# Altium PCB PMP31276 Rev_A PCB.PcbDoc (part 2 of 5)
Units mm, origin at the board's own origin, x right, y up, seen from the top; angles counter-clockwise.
Board outline 228.6 x 203.2 mm, 4 copper layers (Top Layer, Layer 1, Layer 2, Bottom Layer), stack 1.998 mm thick; 375 components, 187 nets, 994 pads, 546 vias.
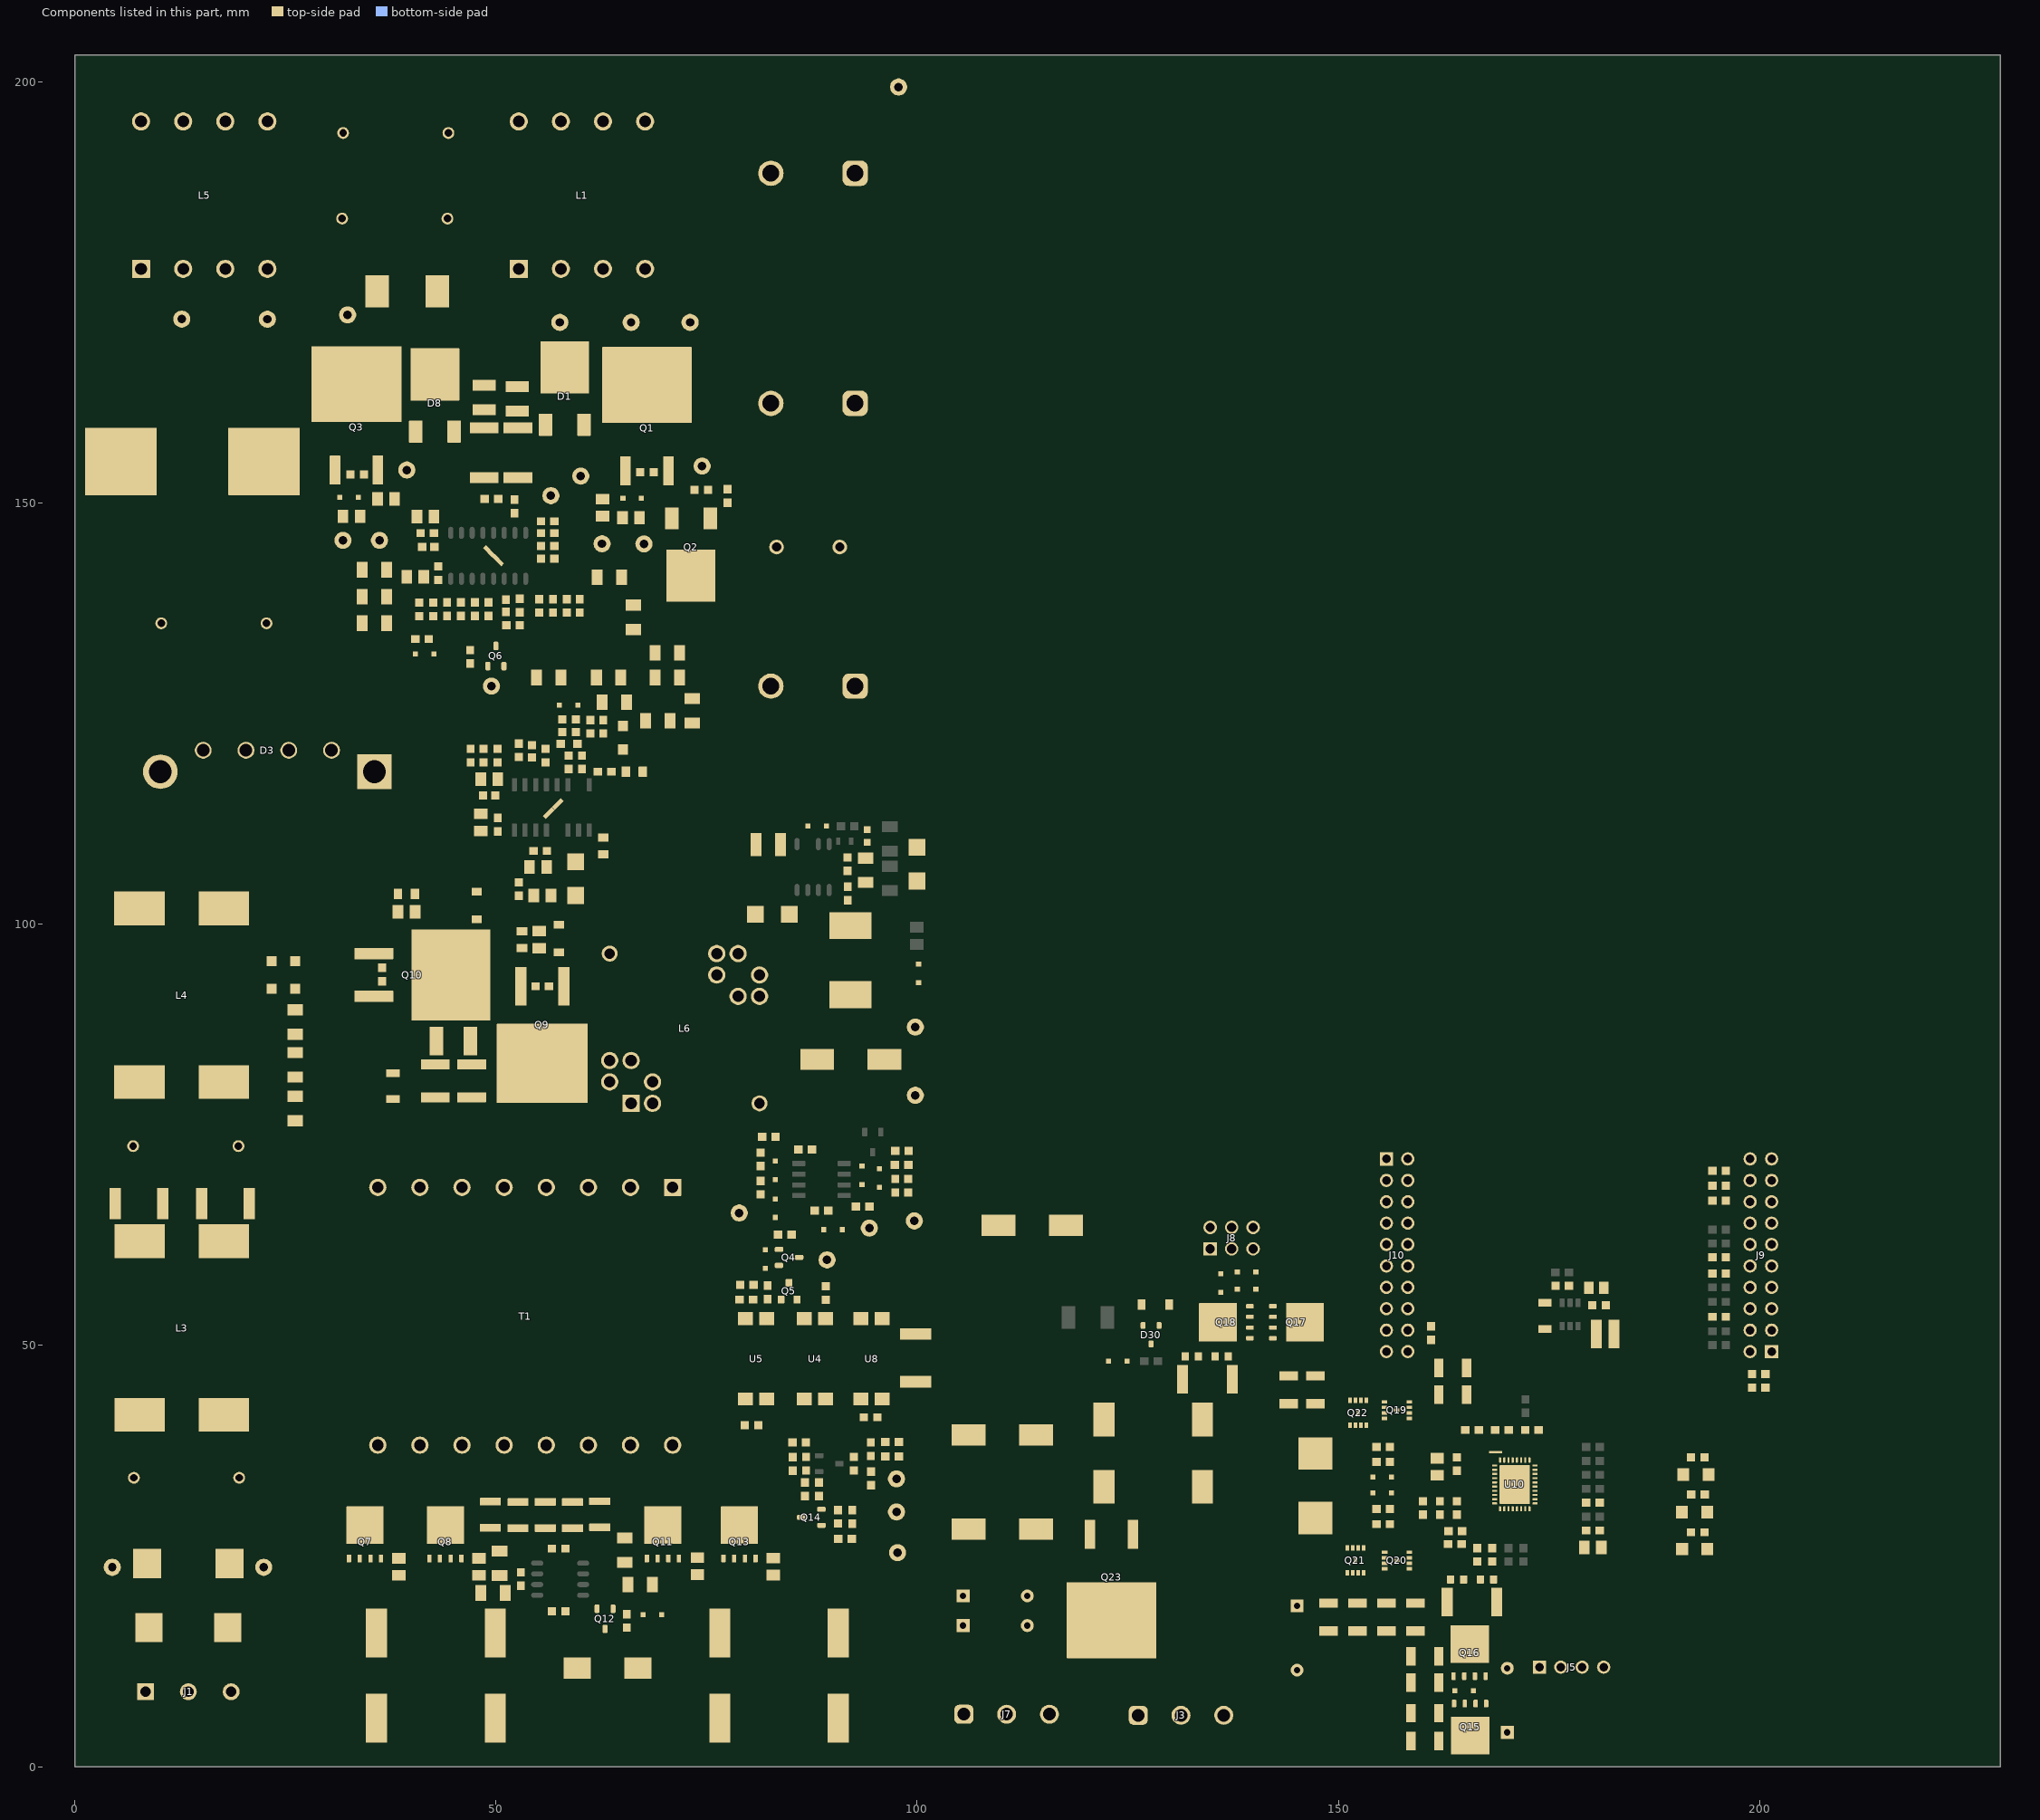
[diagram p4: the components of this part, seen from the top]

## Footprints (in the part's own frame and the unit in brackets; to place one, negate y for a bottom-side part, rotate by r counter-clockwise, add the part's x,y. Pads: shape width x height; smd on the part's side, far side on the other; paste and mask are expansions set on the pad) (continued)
FP-750314724_PTH_XFRMR_23MM5_26MM0-MFG [mm]
  rrect5% 2.15x2.15 hole 1.4 paste-2539.97 mask+0: 1(-8.75,7.5)
  round 2.15 hole 1.4 paste-2539.97 mask+0: 2(-8.75,2.5) 3(-8.75,-2.5) 4(-8.75,-7.5) 5(8.75,-7.5) 6(8.75,-2.5) 7(8.75,2.5) 8(8.75,7.5)
  silkscreen extent -12.47,-13 11.75,13, body extent -11.85,-13.1 11.85,13.1, height 0.25
FP-750371772r00_PTH16_41MM9_44MM0-MFG [mm]
  rrect5% 2.05x2.05 hole 1.35 paste-2539.97 mask+0: 1(-15.3,17.5)
  round 2.05 hole 1.35 paste-2539.97 mask+0: 2(-15.3,12.5) 3(-15.3,7.5) 4(-15.3,2.5) 5(-15.3,-2.5) 6(-15.3,-7.5) 7(-15.3,-12.5) 8(-15.3,-17.5) 9(15.3,-17.5) 10(15.3,-12.5) 11(15.3,-7.5) 12(15.3,-2.5) 13(15.3,2.5) 14(15.3,7.5) 15(15.3,12.5) 16(15.3,17.5)
  silkscreen extent -21.67,-22 20.95,22, body extent -21.05,-22.1 21.05,22.1, height 0.25
FP-750371775r00_PTH_22MM0_22MM0-MFG [mm]
  rrect5% 2.05x2.05 hole 1.35 paste-2539.97 mask+0: 1(-8.89,6.35)
  round 2.05 hole 1.35 paste-2539.97 mask+0: 2(-8.89,3.81) 3(-6.35,3.81) 4(3.81,-6.35) 5(3.81,-8.89) 6(6.35,-8.89) 7(8.89,-6.35) 8(8.89,-3.81) 9(6.35,-3.81) 10(-3.81,6.35) 11(-3.81,8.89) 12(-6.35,8.89)
  round 1.9 hole 1.25 paste-2539.97 mask+0: 13(8.89,8.89) 14(-8.89,-8.89)
  silkscreen extent -11.72,-11 11,11, body extent -11.1,-11.1 11.1,11.1, height 0.25
FP-7443081030_SMT_IND_9MM4_6MM2-MFG [mm]
  rrect4% 3.2x2.54 smd paste+0 mask+0: 1(-3.6,0) 2(3.6,0)
  silkscreen extent -5.9,-3.25 4.85,3.25, body extent -5.3,-3.35 5.3,3.35, height 0.25
FP-560050316012_0603-IPC_B [mm]
  rrect12% 0.86x0.962 smd paste+0 mask+0: 1(-0.776,0) 2(0.776,0)
  silkscreen extent -1.21,-0.88 1.21,0.88, body extent -1.46,-0.73 1.46,0.73, height 0.25
FP-885012206125_0603-IPC_B [mm]
  rrect10% 1.032x0.96 smd paste+0 mask+0: 1(-0.714,0) 2(0.714,0)
  silkscreen extent -1.23,-0.88 1.23,0.88, body extent -1.48,-0.73 1.48,0.73, height 0.25
FP-885012208094_1206-MFG [mm]
  rrect11% 0.9x1.6 smd paste+0 mask+0: 1(-1.55,0) 2(1.55,0)
  silkscreen extent -0.72,-0.95 0.72,0.95, body extent -2.1,-1.05 2.1,1.05, height 0.25
FP-885012209073_1210-MFG [mm]
  rrect11% 0.9x2.5 smd paste+0 mask+0: 1(-1.55,0) 2(1.55,0)
  silkscreen extent -0.72,-1.4 0.72,1.4, body extent -2.1,-1.5 2.1,1.5, height 0.25
FP-B57371V2474J060_0603-MFG [mm]
  rrect10% 1x1 smd paste+0 mask+0: 1(-1,0) 2(1,0)
  silkscreen extent -0.13,-0.48 0.13,0.48, body extent -1.6,-0.6 1.6,0.6, height 0.25
FP-BSS84LT1G_SOT-23-3-318-08-MFG [mm]
  rrect13% 0.9x0.8 smd paste+0 mask+0: 1(-1,0.95) 2(-1,-0.95) 3(1,0)
  silkscreen extent -0.7,-1.52 0.7,1.52, body extent -1.55,-1.62 1.55,1.62, height 0.25
FP-C0603C221J5GAC7867_0603-IPC_B [mm]
  rrect10% 1.007x0.958 smd paste+0 mask+0: 1(-0.726,0) 2(0.726,0)
  silkscreen extent -1.23,-0.88 1.23,0.88, body extent -1.48,-0.73 1.48,0.73, height 0.25
FP-CKC18C103KWGACAUTO_1812-MFG [mm]
  rrect8% 1.2x3.4 smd paste+0 mask+0: 1(-1.95,0) 2(1.95,0)
  silkscreen extent -0.97,-1.75 0.97,1.75, body extent -2.65,-1.85 2.65,1.85, height 0.25
FP-IPB60R105CFD7ATMA1_D2PAK-MFG [mm]
  rrect7% 1.35x4.6 smd paste-1000 mask+0: 1(-2.54,-5.775) 3(2.54,-5.775)
  rrect1% 10.8x9.4 smd paste-1000 mask+0: 4(0,3.375)
  silkscreen extent -5.1,-2.73 5.1,-1.7, body extent -5.5,-8.18 5.5,8.18, height 0.25
FP-ISC0603NLSATMA1_TDSON-8-MFG [mm]
  rrect20% 0.5x0.925 smd paste-1000 mask+0: 1(-1.905,-2.865) 2(-0.635,-2.865) 3(0.635,-2.865) 4(1.905,-2.865)
  rrect2% 4.41x4.455 smd paste-1000 mask+0: 5-6-7-8(0,1.098)
  silkscreen extent -2.68,-4.03 2.68,3.05, body extent -2.78,-3.43 2.78,3.42, height 0.25
FP-SF-3812F1500T-2_3812-MFG [mm]
  rrect3% 3.25x3.43 smd paste+0 mask+0: 1(-4.675,0) 2(4.675,0)
  silkscreen extent -2.68,-1.65 2.68,1.65, body extent -6.4,-1.82 6.4,1.82, height 0.25
FP-V9733E1-LP_THERMAL_HEATSINK_25MM0_42MM0-MFG [mm]
  rrect2% 4.1x4.1 hole 2.7 paste-2539.97 mask+0: 1(-12.7,-0.5)
  round 4.1 hole 2.7 paste-2539.97 mask+0: 2(12.7,-0.5)
  silkscreen extent -21.12,-12.62 21.12,12.62, body extent -21.22,-12.73 21.22,12.73, height 0.25
GBU [mm] "Comchip / Diodes Inc diode bridge"
  round 2 hole 1.5: 1(-7.62,0) 2(-2.54,0) 3(2.54,0) 4(7.62,0)
  silkscreen extent -11.15,-2.28 11.15,1.28, body extent -11.15,-2.28 11.15,1.28, height 21.55
IEC_HighVoltage_Small [mm]
  silkscreen extent -2.72,-2.24 2.72,2.47
IEC_HotSurface_Small [mm]
  silkscreen extent -2.72,-2.36 2.72,2.35
Keystone5000 [mil] "For Keystone 500x miniature loop terminals"
  round 80 hole 40: 1(0,0)
  silkscreen extent -52,-52 52,52, body extent -49,-49 49,49, height 182
Keystone5001 [mil] "For Keystone 500x miniature loop terminals"
  round 80 hole 40: 1(0,0)
  silkscreen extent -52,-52 52,52, body extent -49,-49 49,49, height 182
Keystone5002 [mil] "For Keystone 500x miniature loop terminals"
  round 80 hole 40: 1(0,0)
  silkscreen extent -52,-52 52,52, body extent -49,-49 49,49, height 182
Keystone5004 [mil] "For Keystone 500x miniature loop terminals"
  round 80 hole 40: 1(0,0)
  silkscreen extent -52,-52 52,52, body extent -49,-49 49,49, height 182
Mill-Max_999-11-113-10-000000 [mil] "Shorting Jumper, 7.62mm, 2 Position, Gold, TH"
  rect 60x60 hole 30: 1(-150,0)
  round 60 hole 30: 2(150,0)
  silkscreen extent -102,-12 98,12, body extent -161,-11 161,11, height 105
Net-Tie_10milWide_30milLong [mil] "10mil net tie, no solder mask opening, no solder paste"
  rect 30x10 smd paste-5 mask-5: 1(-15,0) 2(15,0)
Net-Tie_20milWide_60milLong [mil] "20mil net tie, no solder mask opening, no solder paste"
  rect 60x20 smd paste-10 mask-10: 1(-30,0) 2(30,0)
On-Shore_ED120_3DS [mm] "ONSHORE"
  rrect5% 2x2 hole 1.25: 1(-5.08,0)
  round 2 hole 1.25: 2(0,0) 3(5.08,0)
  silkscreen extent -8.14,-4 7.5,5, body extent -8.32,-4 7.62,5, height 13
Power_WDFN-8 [mm] "SMD, 8-Leads, Body 3.3x3.3mm, Pitch 0.65mm"
  rect 0.66x0.42 smd: 1(-1.47,0.975) 2(-1.47,0.325) 3(-1.47,-0.325) 4(-1.47,-0.975) 5(1.47,-0.975) 6(1.47,-0.325) 7(1.47,0.325) 8(1.47,0.975) 9(0,0)
  Top Layer region: 0.25,1.73 -0.32,1.73 -0.32,1.185 -0.5,1.185 -0.5,-1.185 -0.32,-1.185 -0.32,-1.73 0.25,-1.73 0.25,-1.185 1.33,-1.185 1.33,1.185 0.25,1.185
  silkscreen extent -1.9,-1.65 1.65,1.75, body extent -1.65,-1.65 1.65,1.65, height 0.81
RRV0036A-MFG [mm]
  rrect40% 0.6x0.25 smd paste+0 mask+0: 1(-2.4,2.25) 2(-2.4,1.75) 3(-2.4,1.25) 4(-2.4,0.75) 5(-2.4,0.25) 6(-2.4,-0.25) 7(-2.4,-0.75) 8(-2.4,-1.25) 9(-2.4,-1.75) 10(-2.4,-2.25) 19(2.4,-2.25) 20(2.4,-1.75) 21(2.4,-1.25) 22(2.4,-0.75) 23(2.4,-0.25) 24(2.4,0.25) 25(2.4,0.75) 26(2.4,1.25) 27(2.4,1.75) 28(2.4,2.25)
  rrect40% 0.25x0.6 smd paste+0 mask+0: 11(-1.75,-2.9) 12(-1.25,-2.9) 13(-0.75,-2.9) 14(-0.25,-2.9) 15(0.25,-2.9) 16(0.75,-2.9) 17(1.25,-2.9) 18(1.75,-2.9) 29(1.75,2.9) 30(1.25,2.9) 31(0.75,2.9) 32(0.25,2.9) 33(-0.25,2.9) 34(-0.75,2.9) 35(-1.25,2.9) 36(-1.75,2.9)
  rrect3% 3.6x4.6 smd paste-1000 mask+0: 37(0,0)
  silkscreen extent -3.4,-3.05 2.55,3.05, body extent -2.8,-3.3 2.8,3.3, height 0.25
S237 [mm] "EPCOS"
  round 1.75 hole 1.1: 1(-3.75,0) 2(3.75,0)
  silkscreen extent -7.5,-3.5 7.5,3.5, body extent -7.47,-3.5 7.47,3.5, height 21.99
SM_RADIAL_10BMM [mm] "Nichicon 10x10"
  rect 4x2.5 smd: 1(-4,0) 2(4,0)
  silkscreen extent -5.25,-5.25 5.25,5.25, body extent -5.25,-5.25 5.25,5.25, height 10.5
SMA [mm] "Molded Diode, 2-Leads, Body 4.3x2.6mm, IPC Medium Density, based on OnSemi component dimensions and land pattern"
  rect 2x2 smd: 1(-2,0) 2(2,0)
  silkscreen extent -3.66,-1.57 2.79,1.57, body extent -2.6,-1.3 2.6,1.3, height 2.42
SMC [mil] "Molded Diode, 2-Leads, Body 6.9x5.8mm, IPC Medium Density, based on OnSemi component dimensions and land patterns"
  rect 110x150 smd: 1(-140.49,0) 2(140.49,0)
  silkscreen extent -221,-123 189,124, body extent -156,-116 156,116, height 91
SMD-4 [mm] "SMD, 4-Leads, Body 4.83x6.81mm, Pitch 2.54mm"
  rect 1.525x1.78 smd: 1(-4.763,1.27) 2(-4.763,-1.27) 3(4.763,-1.27) 4(4.763,1.27)
  silkscreen extent -3.5,-2.42 3.41,2.8, body extent -5.02,-2.42 5.02,2.42, height 3.91
SOD-123 [mm] "On Semi recommended land pattern"
  rect 0.915x1.22 smd: 1(-1.637,0) 2(1.637,0)
  silkscreen extent -2.74,-1.17 2.03,1.17, body extent -1.93,-0.9 1.93,0.9, height 1.35
SOD-123F [mm] "NXP recommended land pattern"
  rect 1.2x1.2 smd paste-0.05: 1(-1.4,0) 2(1.4,0)
  silkscreen extent -2.64,-1.12 2.01,1.12, body extent -1.8,-0.85 1.8,0.85, height 1.2
SOD-323 [mm] "NXP recommended land pattern"
  rect 0.6x0.6 smd paste-0.05: 1(-1.1,0) 2(1.1,0)
  silkscreen extent -2.06,-0.86 1.53,0.86, body extent -1.3,-0.67 1.3,0.68, height 1.1
SOD-323F [mm] "NXP recommended land pattern"
  rect 0.6x0.6 smd paste-0.05: 1(-1.1,0) 2(1.1,0)
  silkscreen extent -2.06,-0.86 1.53,0.86, body extent -1.35,-0.67 1.35,0.68, height 0.79
SOT-23 [mm] "SOT23, 3-Leads, Body 2.9x1.3mm, Pitch 0.95mm, Lead Span 2.5mm, IPC Medium Density"
  rrect50% 1x0.6 smd: 1(-1.2,0.95) 2(-1.2,-0.95) 3(1.2,0)
  silkscreen extent -1.63,-1.5 0.7,1.5, body extent -1.16,-1.45 1.21,1.45, height 1
SOT-23L [mm] "SOT23, 3-Leads, Body 2.9x1.3mm, Pitch 0.95mm, Lead Span 2.5mm, IPC High Density"
  rrect50% 0.8x0.6 smd: 1(-1.1,0.95) 2(-1.1,-0.95) 3(1.1,0)
  silkscreen extent -1.5,-1.5 0.7,1.5, body extent -1.16,-1.45 1.21,1.45, height 1
VAR_SM7-Series_H [mm] "Littelfuse"
  rect 3.3x3.5 smd: 1(-4.9,0) 2(4.9,0)
  silkscreen extent -6.85,-1.55 6.85,1.57, body extent -5.9,-4.3 5.9,4.3, height 6.3
WCAP-AI3H_D25H30 [mm] "Aluminium Electrolytic Snap-In Capacitors, 25x30mm"
  rrect50% 3x3 hole 2: 1(5,0)
  round 3 hole 2: 2(-5,0)
  silkscreen extent -13,-13 13,13, body extent -12.46,-12.5 12.5,12.5, height 30.09
WCAP-ASLL_D12.5H14 [mm] "Aluminium Electrolytic V-Chip SMT Capacitors, 12.5x14mm"
  rect 5.8x2.5 smd: 1(5.05,0) 2(-5.05,0)
  silkscreen extent -6.85,-6.85 6.85,6.85, body extent -7.1,-6.72 7.1,6.73, height 14
WCAP-CSGP_0603_L1.6W0.8H0.8_Reflow [mm] "Ceramic Capacitors, body 1.6x0.8mm"
  rect 0.8x0.8 smd: 1(-0.75,0) 2(0.75,0)
  body extent -0.8,-0.4 0.8,0.4, height 0.8
WCAP-CSMH_1206_L3.2W1.6H1.25 [mm] "Ceramic Capacitors, body 3.2x1.6mm"
  rect 0.9x1.6 smd: 1(-1.55,0) 2(1.55,0)
  silkscreen extent -0.75,-0.87 0.75,0.87, body extent -1.6,-0.8 1.6,0.8, height 1.25
WCAP-CSSA_2211_L5.7W2.8H2.5 [mm] "Ceramic Capacitors, body 5.70x2.80mm"
  rect 1.35x3.7 smd: 1(-2.825,0) 2(2.825,0)
  silkscreen extent -1.8,-1.55 1.8,1.55, body extent -2.85,-1.4 2.85,1.4, height 2.5
WCAP-FTXX_L15W8.5H14 [mm] "Film Capacitors, 15x8.5x14mm"
  round 1.4 hole 0.9: 1(-6.25,0) 2(6.25,0)
  silkscreen extent -7.75,-4.5 7.75,4.5, body extent -7.5,-4.25 7.5,4.25, height 14.05
WE-HC6 [mm] "Wurth Electronik recommended land pattern"
  rect 3.85x4 smd: 1(-3.825,0) 2(3.825,0)
  silkscreen extent -6.2,-6.2 6.2,6.2, body extent -5.76,-5.36 5.74,5.34, height 5
"WE-HCF Round_2920" [mm] "SMT High Current Inductor, 2-Leads, body 28x25mm"
  rrect1% 8.5x8 smd: 1(-8.5,0) 2(8.5,0)
  body extent -11.55,-13.65 11.55,13.65, height 20
WE-MAPI_3015 [mm] "SMT Shielded Power Inductor, body 3x3mm"
  rect 1.3x3.4 smd: 1(-1.05,0) 2(1.05,0)
  Top Layer keep-out region: -0.3,1.7 0.3,1.7 0.3,-1.7 -0.3,-1.7
  body extent -1.5,-1.5 1.5,1.5, height 1.5
"WE-PD HV_1060" [mm] "SMT High Voltage Power Inductor, 2-Leads, body 10x10mm"
  rect 5x3.2 smd: 1(0,-4.1) 2(0,4.1)
  Top Layer keep-out region: -5,5 -5,-5 -2.7,-5 -2.7,-2.3 2.7,-2.3 2.7,-5 5,-5 5,5 2.7,5 2.7,2.3 -2.7,2.3 -2.7,5
  silkscreen extent -5.15,-6.32 5.15,5.15, body extent -5,-5 5,5, height 5.65
WL_SMCW_GREEN_1206 [mm] "SMD, 2-Leads, Body 3.2x1.6mm, Pitch 3mm"
  rect 1.4x1.5 smd: 1(-1.5,0) 2(1.5,0)
  silkscreen extent -2.9,-1.1 2.2,1.1, body extent -1.6,-0.85 1.6,0.85, height 0.78
Wurth_7446631007 [mm] "SMT, 4-Leads, Body 23.3x18.5mm"
  rect 6x4 smd: 1(-5,10.3) 2(-5,-10.3) 3(5,-10.3) 4(5,10.3)
  silkscreen extent -10,-11.5 9,11.5, body extent -9,-12.27 9,12.28, height 11.06
Wurth_61300621121 [mm] "Header, 2.54mm, 3x2, TH"
  rect 1.6x1.6 hole 1.1: 1(-1.27,2.54)
  round 1.6 hole 1.1: 2(1.27,2.54) 3(-1.27,0) 4(1.27,0) 5(-1.27,-2.54) 6(1.27,-2.54)
  silkscreen extent -2.8,-3.82 2.54,3.8, body extent -2.54,-3.82 2.54,3.8, height 7.27
Wurth_691236510003 [mm] "Terminal Block, 5.08mm, 3x1, R/A, TH"
  rrect50% 2.25x2.25 hole 1.5: 1(-5.08,0)
  round 2.25 hole 1.5: 2(0,0) 3(5.08,0)
  body extent -8.22,-5.5 7.62,5.85, height 18

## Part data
C1 C2 C3: library part CMP-0110395-1, "WCAP-AI3H Aluminum Electrolytic Capacitor, Snap-In, D25 x H30mm, 120µF, 450V", Capacitance Tolerance=+/-20%, Leakage Current=697.14uA, Manufacturer="Wurth Elektronik", Operating Temperature Max=105°C, Operating Temperature Min=-25°C, Rated Voltage (DC)=450V, Ripple Current=800mA
C4 C16 C97: library part CMP-0009273-2, "CAP, CERM, 0.01 uF, 500 V, +/- 10%, X7R, 1206", Cap_Case=1206, Manufacturer=Wuerth, TempCo=X7R, Tolerance_%=10%, Value1=Unknown, Value2=500V, ValueDisplayed=0.01uF
C5 C6 C7 C10 C11: library part CMP-0108923-1, "WCAP-FTXX Film Capacitor, THT, L15 x W8.5 x H14mm, 330nF, 310V", Capacitance Tolerance=+/-10%, Insulation Resistance=30000MOhm, Manufacturer="Wurth Elektronik", Operating Temperature Max=105°C, Operating Temperature Min=-40°C, Rate of Voltage Rise=260V/us, Rated Voltage (AC)=310VAC
C8 C12 C39 C40 C41: library part CMP-0097489-1, "10 µF ±10% 50V Ceramic Capacitor X7R 1210 (3225 Metric)", Digikey Part Number=732-885012209073TR-ND, Manufacturer="Wurth Electronics", Mouser Part Number=710-885012209073, Operating Temperature Range="-55°C to +125°C", TempCo=15%, Temperature Characteristic=X7R, Tolerance_%=10%, ValueDisplayed=10uF
C9 C13 C44: library part CMP-0112567-1, "WCAP-CSSA Multilayer Ceramic Chip Safety Capacitor, size 2211, X7R Class II, 2.2nF, 250VAC", Capacitance Tolerance=+/-10%, Case/Size Code=2211, Impulse Voltage=5000VDC, Insulation Resistance=10GOhm, Manufacturer="Wurth Elektronik", Operating Temperature Max=125°C, Operating Temperature Min=-55°C, Rated Voltage (AC)=250V
C14 C69 C70: library part CMP-0007424-4, "CAP, CERM, 0.47 uF, 25 V, +/- 10%, X7R, 0603", Cap_Case=0603, Manufacturer=MuRata, Supplier Part Number 1=490-3291-1-ND, TempCo=X7R, Tolerance_%=10%, Value1=Unknown, Value2=25V, ValueDisplayed=0.47uF
C15 C27 C50 C80 C81 C82 C83 C86 C91 C96 C100: library part CMP-0006837-3, "CAP, CERM, 0.1 uF, 50 V, +/- 10%, X7R, 0603", Cap_Case=0603, Manufacturer="Wurth Elektronik", TempCo=X7R, Tolerance_%=10%, Value1=Unknown, Value2=50V, ValueDisplayed=0.1uF
C17 C45 C46: library part CMP-0007356-5, "CAP, CERM, 2.2 uF, 35 V, +/- 10%, X5R, 0603", Cap_Case=0603, Manufacturer=MuRata, Supplier Part Number 1=490-7204-6-ND, TempCo=X5R, Tolerance_%=10%, Value1=Unknown, Value2=35V, ValueDisplayed=2.2uF
C18 C20 C23 C31 C101 C102 C103: library part CMP-0064933-4, "CAP, CERM, 1000 pF, 50 V,+/- 10%, X7R, 0603", Cap_Case=0603, Manufacturer="Wurth Elektronik", Supplier Part Number 1=732-8001-1-ND, TempCo=X7R, Tolerance_%=10%, Value1=Unknown, Value2=50V, ValueDisplayed=1000pF
C19 C25 C26 C49 C60: library part CMP-0007029-4, "CAP, CERM, 1 uF, 50 V, +/- 10%, X6S, 0603", Cap_Case=0603, Manufacturer=TDK, Supplier Part Number 1=445-7424-1-ND, TempCo=X6S, Tolerance_%=10%, Value1="0.005522 ohm", Value2=50V, ValueDisplayed=1uF
C21 C22: library part CMP-0006919-4, "CAP, CERM, 33 pF, 50 V, +/- 5%, C0G/NP0, 0603", Cap_Case=0603, Manufacturer=Wuerth, TempCo=C0G/NP0, Tolerance_%=5%, Value1=Unknown, Value2=50V, ValueDisplayed=33pF
C24 C53 C56: library part CMP-0045670-1, "220 pF ±5% 50V Ceramic Capacitor C0G, NP0 0603 (1608 Metric)", Digikey Part Number=399-C0603C221J5GAC7867CT-ND, Manufacturer=KEMET, Operating Temperature Range="-55°C to +125°C", TempCo=30ppm/°C, Temperature Characteristic=C0G, Tolerance_%=5%, ValueDisplayed=220pF
C28: library part CMP-0049212-1, "0.22 µF ±5% 50V Ceramic Capacitor X7R 0603 (1608 Metric)", Digikey Part Number=732-885012206125CT-ND, Manufacturer="Wurth Electronics", Mouser Part Number=710-885012206125, Operating Temperature Range="-55°C to +125°C", TempCo=15%, Temperature Characteristic=X7R, Tolerance_%=5%, ValueDisplayed=220nF
C29 C30 C54 C63: library part CMP-0006835-4, "CAP, CERM, 4700 pF, 50 V, +/- 10%, X7R, 0603", Cap_Case=0603, Manufacturer="Wurth Elektronik", Supplier Part Number 1=710-885012206087, TempCo=X7R, Tolerance_%=10%, Value1=Unknown, Value2=50V, ValueDisplayed=4700pF
C32: library part CMP-0009326-2, "CAP, CERM, 0.1 uF, 1000 V, +/- 10%, X7R, 1812", Cap_Case=1812, Manufacturer=Wuerth, TempCo=X7R, Tolerance_%=10%, Value1=Unknown, Value2=1000V, ValueDisplayed=0.1uF
C33 C43: library part CMP-0097104-1, "10000 pF ±5% 1000V Ceramic Capacitor C0G, NP0 1812 (4532 Metric)", Digikey Part Number=399-CKC18C103JDGACAUTODKR-ND, Manufacturer=KEMET, Operating Temperature Range="-55°C to +150°C", TempCo=30ppm/°C, Temperature Characteristic=C0G, Tolerance_%=10%, ValueDisplayed=0.01uF
C34 C47: library part CMP-0008475-2, "CAP, CERM, 330 pF, 100 V, +/- 5%, C0G/NP0, 1206", Cap_Case=1206, Manufacturer=Wuerth, TempCo=C0G/NP0, Tolerance_%=5%, Value1="0.392 ohm", Value2=100V, ValueDisplayed=330pF
C35 C36 C37 C38: library part CMP-0110502-1, "WCAP-ASLL Aluminum Electrolytic Capacitor, V-Chip, D12.5 x H14mm, 680µF, 35V", Capacitance Tolerance=+/-20%, Leakage Current=238uA, Manufacturer="Wurth Elektronik", Operating Temperature Max=105°C, Operating Temperature Min=-55°C, Rated Voltage (DC)=35V, Ripple Current=1150mA
C42: library part CMP-0108719-1, "WCAP-CSMH Multilayer Ceramic Chip Capacitor, Mid and High Voltage, size 1206, X7R Class II, 150pF, 1000VDC", Capacitance Tolerance=10%, Case/Size Code=1206, Insulation Resistance=10GOhm, Manufacturer="Wurth Elektronik", Operating Temperature Max=125°C, Operating Temperature Min=-55°C, Rated Voltage (DC)=1000V
C48 C52: library part CMP-0007885-2, "CAP, CERM, 4.7 uF, 35 V, +/- 10%, X7R, 0805", Cap_Case=0805, Manufacturer=TDK, Supplier Part Number 1=445-7555-1-ND, TempCo=X7R, Tolerance_%=10%, Value1="0.002346 ohm", Value2=35V, ValueDisplayed=4.7uF
C51: library part CMP-0007728-2, "CAP, CERM, 1 uF, 25 V, +/- 10%, X7R, 0805", Cap_Case=0805, Manufacturer=Wuerth, PartNumber=885012207078, TempCo=X7R, Tolerance_%=10%, Value1=Unknown, Value2=25V, ValueDisplayed=1uF
C55 C59: library part CMP-0006822-4, "CAP, CERM, 100 pF, 50 V, +/- 5%, C0G/NP0, 0603", Cap_Case=0603, Manufacturer="Wurth Elektronik", TempCo=C0G/NP0, Tolerance_%=5%, Value1=Unknown, Value2=50V, ValueDisplayed=100pF
C57 C58: library part CMP-0006897-4, "CAP, CERM, 2200 pF, 50 V, +/- 10%, X7R, 0603", Cap_Case=0603, Manufacturer=Kemet, Supplier Part Number 1=1362428, TempCo=X7R, Tolerance_%=10%, Value1=Unknown, Value2=50V, ValueDisplayed=2200pF
C61: library part CMP-0007015-5, "CAP, CERM, 0.047 uF, 50 V, +/- 10%, X5R, 0603", Cap_Case=0603, Manufacturer=TDK, Supplier Part Number 1=445-14155-1-ND, TempCo=X5R, Tolerance_%=10%, Value1="0.049007 ohm", Value2=50V, ValueDisplayed=0.047uF
C62: library part CMP-0006761-4, "CAP, CERM, 10 pF, 50 V, +/- 5%, C0G/NP0, 0603", Cap_Case=0603, Manufacturer=Wuerth, PartNumber=885012006051, TempCo=C0G/NP0, Tolerance_%=5%, Value1="0.403 ohm", Value2=50V, ValueDisplayed=10pF
C64 C65 C66 C67 C71 C72 C73 C74 C75 C76 C77 C78: library part CMP-0081135-1, "CAP, CERM, 10 µF, 50 V,+/- 10%, X7R, 1210", Cap_Case=1210, Manufacturer=Wuerth, TempCo=X7R, Tolerance_%=10%, Value1="0.001 ohm", Value2=50V, ValueDisplayed=10µF
C68 C79 C88 C89 C90 C98: library part CMP-0011092-1, "CAP, AL, 150 uF, 35 V, +/- 20%, 0.1 ohm, SMD", Cap_Case=10x10, Manufacturer=Nichicon, Supplier Part Number 1=493-3956-6-ND, Tolerance_%=20%, Value1="0.1 ohm", Value2=35V, ValueDisplayed=150uF
C84: library part CMP-0007696-2, "CAP, CERM, 4.7 uF, 25 V, +/- 10%, X5R, 0805", Cap_Case=0805, Manufacturer="Wurth Elektronik", TempCo=X5R, Tolerance_%=10%, Value1=Unknown, Value2=25V, ValueDisplayed=4.7uF
C85: library part CMP-0007696-2, "CAP, CERM, 1 uF, 50 V, +/- 10%, X7R, 0805", Cap_Case=0805, Manufacturer="Wurth Elektronik", Supplier Part Number 1=710-885012207103, TempCo=X7R, Tolerance_%=10%, Value1=Unknown, Value2=50V, ValueDisplayed=1uF
C87: library part CMP-0006833-4, "CAP, CERM, 1 uF, 25 V, +/- 10%, X7R, 0603", Cap_Case=0603, Manufacturer="Wurth Elektronik", Supplier Part Number 1=732-7994-1-ND, TempCo=X7R, Tolerance_%=10%, Value1=Unknown, Value2=25V, ValueDisplayed=1uF
C92: library part CMP-0088282-2, "4.7µF ±10% 50V Ceramic Capacitor X7R 1206 (3216 Metric)", Manufacturer="Wurth Electronics", TempCo=15%, Tolerance_%=10%, ValueDisplayed=4.7uF
C93: library part CMP-0078153-1, "CAP, CERM, 22 µF, 10 V,+/- 20%, X5R, 0805", Cap_Case=0805, Manufacturer="Wurth Elektronik", Supplier Part Number 1=732-7621-1-ND, TempCo=X5R, Tolerance_%=20%, Value2=10V, ValueDisplayed=22µF
C94: library part CMP-0008574-2, "CAP, CERM, 10 uF, 25 V, +/- 10%, X7R, 1206", Cap_Case=1206, Manufacturer="Wurth Elektronik", Supplier Part Number 1=732-7574-1-ND, TempCo=X7R, Tolerance_%=10%, Value1=Unknown, Value2=25V, ValueDisplayed=10uF
C95: library part CMP-0111392-1, "WCAP-CSGP Multilayer Ceramic Chip Capacitor, General Purpose, size 0603, NP0, 22pF, 50VDC", Capacitance Tolerance=+/-5%, Case/Size Code=0603, Insulation Resistance=10GOhm, Manufacturer="Wurth Elektronik", Operating Temperature Max=125°C, Operating Temperature Min=-55°C, Rated Voltage (DC)=50V
C99: library part CMP-0064932-4, "CAP, CERM, 1 uF, 10 V,+/- 10%, X7R, 0603", Cap_Case=0603, Manufacturer="Wurth Elektronik", Supplier Part Number 1=732-7945-1-ND, TempCo=X7R, Tolerance_%=10%, Value1=Unknown, Value2=10V, ValueDisplayed=1uF
D1 D8: library part CMP-0079155-3, "Diode, Ultrafast, 600 V, 8 A, DPAK", Manufacturer=Diodes, Value1=8A, Value2=1.05V
D2 D11 D15: library part CMP-0028455-2, "Diode, Schottky, 30 V, 0.2 A, SOD-323", Manufacturer="ON Semiconductor", Value1=0.2A, Value2=0.35V
D3: library part CMP-0029234-3, "Diode, Switching-Bridge, 800 V, 10 A, TH", Manufacturer="Diodes Inc.", Value1=10A, Value2=1V
D4: library part CMP-0082070-2, "Diode, Switching, 600 V, 3 A, SMC", Manufacturer=Vishay-Semiconductor, Value2=1.15V
D5 D6: library part CMP-0082234-2, "Diode, Fast Rectifier, 1000 V, 1 A, SOD-123F", Manufacturer="Diotech Semiconductor AG", Value1=1A, Value2=1.3V
D7 D9 D10 D12 D13 D14: library part CMP-0029150-2, "Diode, Switching, 200 V, 0.2 A, AEC-Q101, SOD-323", Manufacturer="ON Semiconductor", Value1=0.2A, Value2=1.25V
D16 D17: library part CMP-0028624-2, "Diode, Schottky, 40 V, 1 A, SOD-123", Manufacturer=Rohm, PartNumber=RB160MM-40TR, Value1=1A, Value2=0.55V
D18 D37: library part CMP-0085764-1, "Diode, Zener, 16 V, 300 mW, SOD-323", Manufacturer="ON Semiconductor", Power_W=300mW, Value1=0.3W
D19: library part CMP-0077027-2, "Diode, Ultrafast, 600 V, 1 A, SMA", Manufacturer="Diodes Inc.", PartNumber=US1J-13-F, Value2=1.7V
D20: library part CMP-0085765-1, "Diode, Zener, 18 V, 300 mW, AEC-Q101, SOD-323", Manufacturer="ON Semiconductor", Power_W=300mW, Value1=0.3W
D21: library part CMP-0028377-2, "Diode, Schottky, 60 V, 1 A, SOD-123F", Manufacturer=Nexperia, PartNumber=PMEG6010CEH,115, Value1=1A, Value2=0.57V
D22 D25: library part CMP-0005833-4, "Diode, Zener, 15 V, 200 mW, SOD-323", Manufacturer="Central semiconductor", Power_W=200mW, Value1=0.2W
D23 D24 D31 D32 D33 D34: library part CMP-0076946-2, "Diode, Schottky, 100 V, 0.25 A, SOD-323F", Manufacturer=Nexperia, Value1=0.25A, Value2=0.85V
D26 D27 D28: library part CMP-0002936-3, "LED, Green, SMD", Color=Green, Manufacturer="Wurth Elektronik", Power_TotalModule=72mW, Value1=0.072W, Value2=2V
D29: library part CMP-0005786-2, "Diode, Zener, 5.1 V, 500 mW, SOD-123", Manufacturer="ON Semiconductor", Power_W=500mW, Value1=0.5W
D30: library part CMP-0076970-1, "Diode, Schottky, 40 V, 0.2 A, SOT-23", Manufacturer="Diodes Inc.", Supplier Part Number 1=BAS40-04FDICT-ND, Value1=0.2A, Value2=1V
D35: library part CMP-0077053-2, "Diode, Superfast Rectifier, 600 V, 1 A, SMA", Manufacturer="Micro Commercial Components", Value1=1A, Value2=1.7V
D36: library part CMP-0029033-2, "Diode, Ultrafast, 600 V, 1 A, AEC-Q101, SMA", Manufacturer="ON Semiconductor", Value1=1A, Value2=1.05V
F1: library part CMP-0037653-1, "5 A 250 V AC 80 V DC Fuse Board Mount (Cartridge Style Excluded) Surface Mount 2-SMD, Square End Block", Digikey Part Number=SF-3812TL500T-2CT-ND, Fuse Current=5A, Fuse Interrupt Dc Current=50A, Manufacturer=Bourns, Operating Temperature Range="-55°C to +125°C"
H1: library part CMP-0092962-1, "Heat Sink 11 K/W, 25,4x42x25 mm, black anodized, for TO-220", Manufacturer="Assmann WSW components", Mating Package=TO-220, Operating Temperature Range=to, Thermal Resistance Natural Convection=11°C/W
H2 H3 H4 H5 H6 H7: library part CMP-0003620-1, "Bumpon, Hemisphere, 0.44 X 0.20, Clear", Manufacturer=3M, PartNumber="SJ-5303 (CLEAR)", Supplier Part Number 1=SJ5303-7-ND
J1: library part CMP-0074911-1, "Terminal Block, 5.08 mm, 3x1, Brass, TH", Current_A=14A, Manufacturer=Wuerth, Voltage_V=300V
J2 J4 J6 J11: library part CMP-0055045-1, "Shorting Jumper, 7.62mm, 2 Position, Gold, TH", Manufacturer=Mill-Max, Supplier Part Number 1=ED1334-ND
J3 J7: library part CMP-0079043-1, "Terminal Block, 5.08mm, 3x1, R/A, TH", Color=Green, Current_A=20A, Manufacturer="Wurth Elektronik", Supplier Part Number 1=732-10996-ND, Voltage_V=300V
J5: library part CMP-0089047-1, Current_A=4A, Manufacturer=Wuerth, Voltage_V=500V
J8: library part CMP-0054802-2, "Header, 2.54mm, 3x2, Gold, TH", Color=Black, Manufacturer="Wurth Elektronik", Supplier Part Number 1=732-5295-ND
J9: library part LaunchPadPart1, "HTSW - Samtec 2.54mm High-Temp Terminal Strip / Header", Color=Natural, Manufacturer=Samtec, Package Quantity=1, Supplier Part Number 1=SAM10541-ND
J10: library part "launchPad Part2", "HTSW - Samtec 2.54mm High-Temp Terminal Strip / Header", Color=Natural, Manufacturer=Samtec, Package Quantity=1, Supplier Part Number 1=SAM10541-ND
L1 L5: library part CMP-0120631-1, "INDUCTOR", Manufacturer=Wurth, Operating Temperature Range="-40°C to +125°C", Voltage_Isolation_Vrms=1kV
L2: library part CMP-0085391-1, "Inductor, Shielded, Mn-Zn, 220 µH, 5.3 A, 0.040095 ohm, SMD", Manufacturer="Wurth Elektronik", Value1="0.040095 ohm", Value2=5.3A, ValueDisplayed=220µH
L3 L4: library part CMP-0013106-2, "Coupled inductor, 0.7 mH, 5.25 A, 0.03 ohm, SMD", Manufacturer="Wurth Elektronik", ValueDisplayed=0.7mH
L6: library part CMP-0120633-1, "INDUCTOR", Manufacturer=Wurth, Operating Temperature Range="-40°C to +125°C", Test Frequency=10kHz, Tolerance_%=10%
L7: library part CMP-0093738-1, "WE-HCM SMT High Current Flat Wire Inductor 34.6A 300nH @ 10% 100kHz 0.3045mohm", Manufacturer="Wurth Electronics", Operating Temperature Range="-40°C to +125°C", Self Resonant Frequency=33MHz, Test Frequency=100kHz, Tolerance_%=10%
L8: library part CMP-0063967-1, "Inductor, Shielded Drum Core, Superflux, 5.5 uH, 10 A, 0.0112 ohm, SMD", Manufacturer="Wurth Elektronik", Supplier Part Number 1=732-1171-1-ND, Value1="0.0112 ohm", Value2=10A, ValueDisplayed=5.5uH
L9: library part CMP-0099107-1, "WE-MAPI SMT Power Inductor, size 3015, 15uH, 0.65A, 830mOhm", Case/Size Code=3015, DC Resistance=720mOhm, DC Resistance Max=830mOhm, Inductance=15uH, Manufacturer="Wurth Elektronik", Operating Temperature Max=125°C, Operating Temperature Min=-40°C, Rated Current=0.65A, Saturation Current=1.71A, Self Resonant Frequency=14MHz
L10: library part CMP-0101506-1, "WE-PD HV SMT High Voltage Power Inductor, size 1060, 470uH, 0.6A, 1.45Ohm", Case/Size Code=1060, DC Resistance=1.25Ohm, DC Resistance Max=1.45Ohm, Inductance=470uH, Manufacturer="Wurth Elektronik", Operating Temperature Max=125°C, Operating Temperature Min=-40°C, Operating Voltage (DC)=400V, Rated Current=0.6A, Saturation Current=0.8A, Self Resonant Frequency=2.7MHz
LOGO2 LOGO3 LOGO4 LOGO5: library part CMP-0074835-1, "IEC 61010-1 High Voltage Warning"
LOGO6 LOGO7: library part CMP-0074837-1, "IEC 61010-1 Hot Surface Warning"
NT1: library part CMP-0078142-5, "Single point connection between nets.", Manufacturer=N/A
NT2 NT3: library part CMP-0078142-6, "Single point connection between nets.", Manufacturer=N/A
Q1 Q3: library part CMP-0086154-1, "MOSFET, N-CH, 600 V, 13 A, DDPAK", Alternate Manufacturer=None, Manufacturer="Infineon Technologies", Value1="? ohm", Value2="25 nC"
Q2: library part CMP-0079555-2, "MOSFET, N-CH, 600 V, 9 A, DPAK", Alternate Manufacturer=None, Manufacturer="Infineon Technologies", Supplier Part Number 1=IPD60R360P7SAUMA1CT-ND, Value1="? ohm", Value2="13 nC"
Q4: library part CMP-0000419-1, "Transistor, NPN, 40 V, 0.2 A, SOT-23", Manufacturer="ON Semiconductor", Supplier Part Number 1=MMBT3904LT1GOSCT-ND, Value1="0.2 A", Value2=300
Q5: library part CMP-0090761-1, "P-Channel 50V 130mA (Ta) 225mW (Ta) Surface Mount SOT-23-3 (TO-236)", Digikey Part Number=BSS84LT1GOSCT-ND, Drain To Source Breakdown Voltage=-50V, Input Capacitace At Vds="36pF @ 5V", Manufacturer="On Semiconductor", Mouser Part Number=863-BSS84LT1G, Operating Temperature Range="-55°C to +150°C", Power_W=225mW, Pulse Drain Current=-520mA
Q6: library part CMP-0000326-1, "Transistor, PNP, 40 V, 0.2 A, SOT-23", Manufacturer="Diodes Inc.", Supplier Part Number 1=MMBT3906-FDICT-ND, Value1="0.2 A", Value2=400
Q7 Q8 Q11 Q13: library part CMP-0096664-1, "N-Channel 80 V 12.3A (Ta), 56A (Tc) 2.5W (Ta), 52W (Tc) Surface Mount PG-TDSON-8-6", Digikey Part Number=448-ISC0603NLSATMA1CT-ND, Drain To Source Breakdown Voltage=80V, Input Capacitace At Vds="1200pF @ 40V", Manufacturer=Infineon, Mouser Part Number=726-ISC0603NLSATMA1, Operating Temperature Range="-55°C to +150°C", Power_W=2.5W, Pulse Drain Current=224A, Typ Forward Diode Voltage=0.88V
Q9 Q10: library part CMP-0065576-1, "Power Transistor MOSFET N-Channel Enhancement 600V 21A 3-Pin D2PAK T/R", Drain To Source Breakdown Voltage=600V, Input Capacitace At Vds="2103pF @ 400V", Manufacturer=Infineon, Operating Temperature Range="-55°C to +150°C", Power_W=106W, Pulse Drain Current=97A, Typ Forward Diode Voltage=1V
Q12: library part CMP-0000488-2, "Transistor, NPN, 60 V, 0.5 A, AEC-Q101, SOT-23", Manufacturer="ON Semiconductor", Supplier Part Number 1=MMBTA05LT1GOSCT-ND, Value1="0.5 A"
Q14: library part CMP-0074582-1, "MOSFET, N-CH, 50 V, .2 A, AEC-Q101, SOT-23", Alternate Manufacturer=None, Manufacturer="ON Semiconductor", Supplier Part Number 1=BSS138LT3GOSTR-ND, Value1="? ohm", Value2="? nC"
Q15 Q16 Q17 Q18: library part CMP-0000817-1, "MOSFET, N-CH, 60 V, 50 A, DQJ0008A (VSONP-8)", Alternate Manufacturer=None, Manufacturer="Texas Instruments", Supplier Part Number 1=296-35583-1-ND, Value1=0.009, Value2="22 nC"
Q19 Q20 Q21 Q22: library part CMP-0000855-1, "MOSFET, N-CH, 60 V, 70 A, 8-PowerWDFN", Alternate Manufacturer=None, Manufacturer="ON Semiconductor", Value1=0.013, Value2="9 nC"
Q23: library part CMP-0000151-4, "MOSFET, P-CH, -60 V, -110 A, DDPAK", Alternate Manufacturer=None, Manufacturer=Vishay-Siliconix, Value1=0.008, Value2="230 nC"
R1 R15 R48 R49 R50 R54 R55 R59 R63: library part CMP-0020812-2, "RES, 2.2, 5%, 0.125 W, 0805", Manufacturer="Yageo America", Power_W=125mW, Supplier Part Number 1=311-2.2ARCT-ND, TempCo="200 ppm/C", Tolerance_%=5%, Value2=0.125W, Value_Code=2R20, ValueDisplayed=2.2
R2 R10 R17 R22 R32 R53 R57 R81: library part CMP-0021998-4, "RES, 10.0 k, 1%, 0.1 W, AEC-Q200 Grade 0, 0603", Manufacturer=Vishay-Dale, PartNumber=CRCW060310K0FKEA, Power_W=100mW, Supplier Part Number 1=541-10.0KHCT-ND, TempCo="100 ppm/C", Tolerance_%=1%, Value2=0.1W, Value_Code=10k0, ValueDisplayed=10.0k
R3 R18: library part CMP-0020655-3, "RES, 18, 5%, 0.125 W, AEC-Q200 Grade 0, 0805", Manufacturer=Panasonic, Power_W=125mW, Supplier Part Number 1=P18ACT-ND, TempCo="200 ppm/C", Tolerance_%=5%, Value2=0.125W, Value_Code=18R0, ValueDisplayed=18
R4 R5: library part CMP-0015775-2, "RES, 0.03, 1%, 2 W, 2512", Manufacturer="Stackpole Electronics Inc", PartNumber=CSRN2512FK30L0, Power_W=2W, Supplier Part Number 1=CSRN2512FK30L0CT-ND, TempCo="200 ppm/C", Tolerance_%=1%, Value_Code=R030, ValueDisplayed=0.03
R6 R38 R69 R80 R86: library part CMP-0021990-4, "RES, 100 k, 1%, 0.1 W, AEC-Q200 Grade 0, 0603", Manufacturer=Vishay-Dale, Power_W=100mW, Supplier Part Number 1=541-100KHCT-ND, TempCo="100 ppm/C", Tolerance_%=1%, Value2=0.1W, Value_Code=100k
R7: library part CMP-0023068-4, "RES, 390 k, 1%, 0.1 W, 0603", Manufacturer=Yageo, Power_W=100mW, Supplier Part Number 1=311-390KHRCT-ND, TempCo="100 ppm/C", Tolerance_%=1%, Value2=0.1W, Value_Code=390k
R8 R9 R14: library part CMP-0017544-3, "RES, 332 k, 1%, 0.25 W, AEC-Q200 Grade 0, 1206", Manufacturer=Panasonic, Power_W=250mW, Supplier Part Number 1=P332KFCT-ND, TempCo="100 ppm/C", Tolerance_%=1%, Value2=0.25W, Value_Code=332k
R11 R16 R21 R43 R44 R45: library part CMP-0016729-3, "RES, 1.37 M, 1%, 0.25 W, AEC-Q200 Grade 0, 1206", Manufacturer=Vishay-Dale, Power_W=250mW, Supplier Part Number 1=541-1.37MFCT-ND, TempCo="100 ppm/C", Tolerance_%=1%, Value2=0.25W, Value_Code=1M37, ValueDisplayed=1.37M
R12 R39 R121 R122 R123 R124 R131: library part CMP-0023152-5, "RES, 4.75 k, 1%, 0.1 W, 0603", Manufacturer=Yageo, Power_W=100mW, Supplier Part Number 1=311-4.75KHRCT-ND, TempCo="100 ppm/C", Tolerance_%=1%, Value2=0.1W, Value_Code=4k75, ValueDisplayed=4.75k
R13 R115: library part CMP-0022925-5, "RES, 22.0 k, 1%, 0.1 W, 0603", Manufacturer=Yageo, Power_W=100mW, Supplier Part Number 1=311-22.0KHRCT-ND, TempCo="100 ppm/C", Tolerance_%=1%, Value2=0.1W, Value_Code=22k0, ValueDisplayed=22.0k
R19: library part CMP-0023050-5, "RES, 35.7 k, 1%, 0.1 W, 0603", Manufacturer=Yageo, Power_W=100mW, Supplier Part Number 1=311-35.7KHRCT-ND, TempCo="100 ppm/C", Tolerance_%=1%, Value2=0.1W, Value_Code=35k7, ValueDisplayed=35.7k
R20: library part CMP-0022691-3, "RES, 20.0 k, 1%, 0.1 W, AEC-Q200 Grade 0, 0603", Manufacturer=Panasonic, Power_W=100mW, Supplier Part Number 1=P20.0KHCT-ND, TempCo="100 ppm/C", Tolerance_%=1%, Value2=0.1W, Value_Code=20k0, ValueDisplayed=20.0k
R23: library part CMP-0023001-4, "RES, 2.21 M, 1%, 0.1 W, 0603", Manufacturer=Yageo, Power_W=100mW, Supplier Part Number 1=311-2.21MHRCT-ND, TempCo="100 ppm/C", Tolerance_%=1%, Value2=0.1W, Value_Code=2M21, ValueDisplayed=2.21M
R24: library part CMP-0022803-5, "RES, 14.7 k, 1%, 0.1 W, 0603", Manufacturer=Yageo, Power_W=100mW, Supplier Part Number 1=311-14.7KHRCT-ND, TempCo="100 ppm/C", Tolerance_%=1%, Value2=0.1W, Value_Code=14k7, ValueDisplayed=14.7k
R25 R27 R29 R66 R68 R71: library part CMP-0016960-3, "RES, 3.32 M, 1%, 0.25 W, AEC-Q200 Grade 0, 1206", Manufacturer=Vishay-Dale, Power_W=250mW, Supplier Part Number 1=541-3.32MFCT-ND, TempCo="100 ppm/C", Tolerance_%=1%, Value2=0.25W, Value_Code=3M32, ValueDisplayed=3.32M
R26: library part CMP-0022772-4, "RES, 124 k, 1%, 0.1 W, 0603", Manufacturer=Yageo, Power_W=100mW, Supplier Part Number 1=311-124KHRCT-ND, TempCo="100 ppm/C", Tolerance_%=1%, Value2=0.1W, Value_Code=124k
R28: library part CMP-0021991-4, "RES, 100, 1%, 0.1 W, AEC-Q200 Grade 0, 0603", Manufacturer=Vishay-Dale, PartNumber=CRCW0603100RFKEA, Power_W=100mW, Supplier Part Number 1=541-100HCT-ND, TempCo="100 ppm/C", Tolerance_%=1%, Value2=0.1W, Value_Code=100R, ValueDisplayed=100
R30 R31: library part CMP-0021530-3, "RES, 10.7 k, 1%, 0.125 W, AEC-Q200 Grade 0, 0805", Manufacturer=Panasonic, Power_W=125mW, Supplier Part Number 1=P10.7KCCT-ND, TempCo="100 ppm/C", Tolerance_%=1%, Value2=0.125W, Value_Code=10k7, ValueDisplayed=10.7k
R33: library part CMP-0022812-4, "RES, 158 k, 1%, 0.1 W, 0603", Manufacturer=Yageo, Power_W=100mW, Supplier Part Number 1=311-158KHRCT-ND, TempCo="100 ppm/C", Tolerance_%=1%, Value2=0.1W, Value_Code=158k
R34 R85 R102: library part CMP-0022816-5, "RES, 15.0 k, 1%, 0.1 W, 0603", Manufacturer=Yageo, Power_W=100mW, Supplier Part Number 1=311-15.0KHRCT-ND, TempCo="100 ppm/C", Tolerance_%=1%, Value2=0.1W, Value_Code=15k0, ValueDisplayed=15.0k
R35 R47: library part CMP-0023132-5, "RES, 47.5 k, 1%, 0.1 W, 0603", Manufacturer=Yageo, Power_W=100mW, Supplier Part Number 1=311-47.5KHRCT-ND, TempCo="100 ppm/C", Tolerance_%=1%, Value2=0.1W, Value_Code=47k5, ValueDisplayed=47.5k
R36: library part CMP-0022901-4, "RES, 200 k, 1%, 0.1 W, 0603", Manufacturer=Yageo, Power_W=100mW, Supplier Part Number 1=311-200KHRCT-ND, TempCo="100 ppm/C", Tolerance_%=1%, Value2=0.1W, Value_Code=200k
R37: library part CMP-0022846-4, "RES, 182 k, 1%, 0.1 W, 0603", Manufacturer=Yageo, Power_W=100mW, Supplier Part Number 1=311-182KHRCT-ND, TempCo="100 ppm/C", Tolerance_%=1%, Value2=0.1W, Value_Code=182k
R40: library part CMP-0022971-4, "RES, 287 k, 1%, 0.1 W, 0603", Manufacturer=Yageo, Power_W=100mW, Supplier Part Number 1=311-287KHRCT-ND, TempCo="100 ppm/C", Tolerance_%=1%, Value2=0.1W, Value_Code=287k
R41: library part CMP-0022958-5, "RES, 26.7 k, 1%, 0.1 W, 0603", Manufacturer=Yageo, Power_W=100mW, Supplier Part Number 1=311-26.7KHRCT-ND, TempCo="100 ppm/C", Tolerance_%=1%, Value2=0.1W, Value_Code=26k7, ValueDisplayed=26.7k
R42 R46: library part CMP-0023285-5, "RES, 80.6 k, 1%, 0.1 W, 0603", Manufacturer=Yageo, Power_W=100mW, Supplier Part Number 1=311-80.6KHRCT-ND, TempCo="100 ppm/C", Tolerance_%=1%, Value2=0.1W, Value_Code=80k6, ValueDisplayed=80.6k
R51 R56 R73: library part CMP-0020448-3, "RES, 10, 5%, 0.125 W, AEC-Q200 Grade 0, 0805", Manufacturer=Vishay-Dale, PartNumber=CRCW080510R0JNEA, Power_W=125mW, Supplier Part Number 1=541-10ACT-ND, TempCo="200 ppm/C", Tolerance_%=5%, Value2=0.125W, Value_Code=10R0, ValueDisplayed=10
R52 R62: library part CMP-0018087-2, "RES, 22.0, 1%, 0.25 W, 1206", Manufacturer="Yageo America", Power_W=250mW, Supplier Part Number 1=311-22.0FRCT-ND, TempCo="100 ppm/C", Tolerance_%=1%, Value2=0.25W, Value_Code=22R0, ValueDisplayed=22.0
R58: library part CMP-0020904-3, "RES, 150, 1%, 0.125 W, AEC-Q200 Grade 0, 0805", Manufacturer=Vishay-Dale, Power_W=125mW, Supplier Part Number 1=541-150CCT-ND, TempCo="100 ppm/C", Tolerance_%=1%, Value2=0.125W, Value_Code=150R, ValueDisplayed=150
R60: library part CMP-0023252-5, "RES, 6.81 k, 1%, 0.1 W, 0603", Manufacturer=Yageo, Power_W=100mW, Supplier Part Number 1=311-6.81KHRCT-ND, TempCo="100 ppm/C", Tolerance_%=1%, Value2=0.1W, Value_Code=6k81, ValueDisplayed=6.81k
R61 R82 R91 R92 R94 R95 R98 R119: library part CMP-0023343-3, "RES, 0, 1%, 0.1 W, AEC-Q200 Grade 0, 0603", Manufacturer="Stackpole Electronics Inc", Power_W=100mW, Supplier Part Number 1=RMCF0603ZT0R00CT-ND, TempCo=ppm/C, Tolerance_%=1%, Value2=0.1W, Value_Code=0
R64: library part CMP-0023226-4, "RES, 649 k, 1%, 0.1 W, 0603", Manufacturer=Yageo, Power_W=100mW, Supplier Part Number 1=311-649KHRCT-ND, TempCo="100 ppm/C", Tolerance_%=1%, Value2=0.1W, Value_Code=649k
R65: library part CMP-0023143-5, "RES, 49.9, 1%, 0.1 W, 0603", Manufacturer=Yageo, Power_W=100mW, Supplier Part Number 1=311-49.9HRCT-ND, TempCo="100 ppm/C", Tolerance_%=1%, Value2=0.1W, Value_Code=49R9, ValueDisplayed=49.9
R67: library part CMP-0022822-4, "RES, 162 k, 1%, 0.1 W, 0603", Manufacturer=Yageo, Power_W=100mW, Supplier Part Number 1=311-162KHRCT-ND, TempCo="100 ppm/C", Tolerance_%=1%, Value2=0.1W, Value_Code=162k
R70 R78: library part CMP-0022558-4, "RES, 6.04 k, 1%, 0.1 W, AEC-Q200 Grade 0, 0603", Manufacturer=Vishay-Dale, PartNumber=CRCW06036K04FKEA, Power_W=100mW, Supplier Part Number 1=541-6.04KHCT-ND, TempCo="100 ppm/C", Tolerance_%=1%, Value2=0.1W, Value_Code=6k04, ValueDisplayed=6.04k
R72 R84 R104 R105 R106: library part CMP-0022895-5, "RES, 1.00 k, 1%, 0.1 W, 0603", Manufacturer=Yageo, Power_W=100mW, Supplier Part Number 1=311-1.00KHRCT-ND, TempCo="100 ppm/C", Tolerance_%=1%, Value2=0.1W, Value_Code=1k00, ValueDisplayed=1.00k
R74: library part CMP-0022784-4, "RES, 130 k, 1%, 0.1 W, 0603", Manufacturer=Yageo, Power_W=100mW, Supplier Part Number 1=311-130KHRCT-ND, TempCo="100 ppm/C", Tolerance_%=1%, Value2=0.1W, Value_Code=130k
R75: library part CMP-0022957-5, "RES, 26.1 k, 1%, 0.1 W, 0603", Manufacturer=Yageo, Power_W=100mW, Supplier Part Number 1=311-26.1KHRCT-ND, TempCo="100 ppm/C", Tolerance_%=1%, Value2=0.1W, Value_Code=26k1, ValueDisplayed=26.1k
R76: library part CMP-0023056-5, "RES, 36.5 k, 1%, 0.1 W, 0603", Manufacturer=Yageo, Power_W=100mW, Supplier Part Number 1=311-36.5KHRCT-ND, TempCo="100 ppm/C", Tolerance_%=1%, Value2=0.1W, Value_Code=36k5, ValueDisplayed=36.5k
R77: library part CMP-0096703-1, "NTC Thermistor 470k 0603 (1608 Metric)", B Tolerance=3%, Digikey Part Number=495-B57371V2474J060CT-ND, Manufacturer=TDK, Mouser Part Number=871-B57371V2474J060, Operating Temperature Range="-55°C to +125°C", Power_W=180mW, Tolerance_%=5%
R79: library part CMP-0022777-5, "RES, 12.4 k, 1%, 0.1 W, 0603", Manufacturer=Yageo, Power_W=100mW, Supplier Part Number 1=311-12.4KHRCT-ND, TempCo="100 ppm/C", Tolerance_%=1%, Value2=0.1W, Value_Code=12k4, ValueDisplayed=12.4k
R83: library part CMP-0023326-5, "RES, 95.3 k, 1%, 0.1 W, 0603", Manufacturer=Yageo, Power_W=100mW, Supplier Part Number 1=311-95.3KHRCT-ND, TempCo="100 ppm/C", Tolerance_%=1%, Value2=0.1W, Value_Code=95k3, ValueDisplayed=95.3k
R87: library part CMP-0015819-2, "RES, 0.002, 1%, 2 W, 2512", Manufacturer=Wuerth, Power_W=2W, TempCo=ppm/C, Tolerance_%=1%, Value_Code=2L000, ValueDisplayed=0.002
R88 R89 R93 R97: library part CMP-0087986-1, "WRIS-KSKE Thick Film Resistors", Manufacturer="Wurth Electronics", Power_W=250mW, TempCo=100ppm/°C, Tolerance_%=1%
R90: library part CMP-0022436-4, "RES, 475 k, 1%, 0.1 W, AEC-Q200 Grade 0, 0603", Manufacturer=Vishay-Dale, Power_W=100mW, Supplier Part Number 1=541-475KHCT-ND, TempCo="100 ppm/C", Tolerance_%=1%, Value2=0.1W, Value_Code=475k
R96: library part CMP-0015814-2, "RES, 0.005, 1%, 2 W, 2512", Manufacturer=Wuerth, Power_W=2W, TempCo="100 ppm/C", Tolerance_%=1%, Value_Code=5L000, ValueDisplayed=0.005
R99: library part CMP-0022754-4, "RES, 113 k, 1%, 0.1 W, 0603", Manufacturer=Yageo, Power_W=100mW, Supplier Part Number 1=311-113KHRCT-ND, TempCo="100 ppm/C", Tolerance_%=1%, Value2=0.1W, Value_Code=113k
